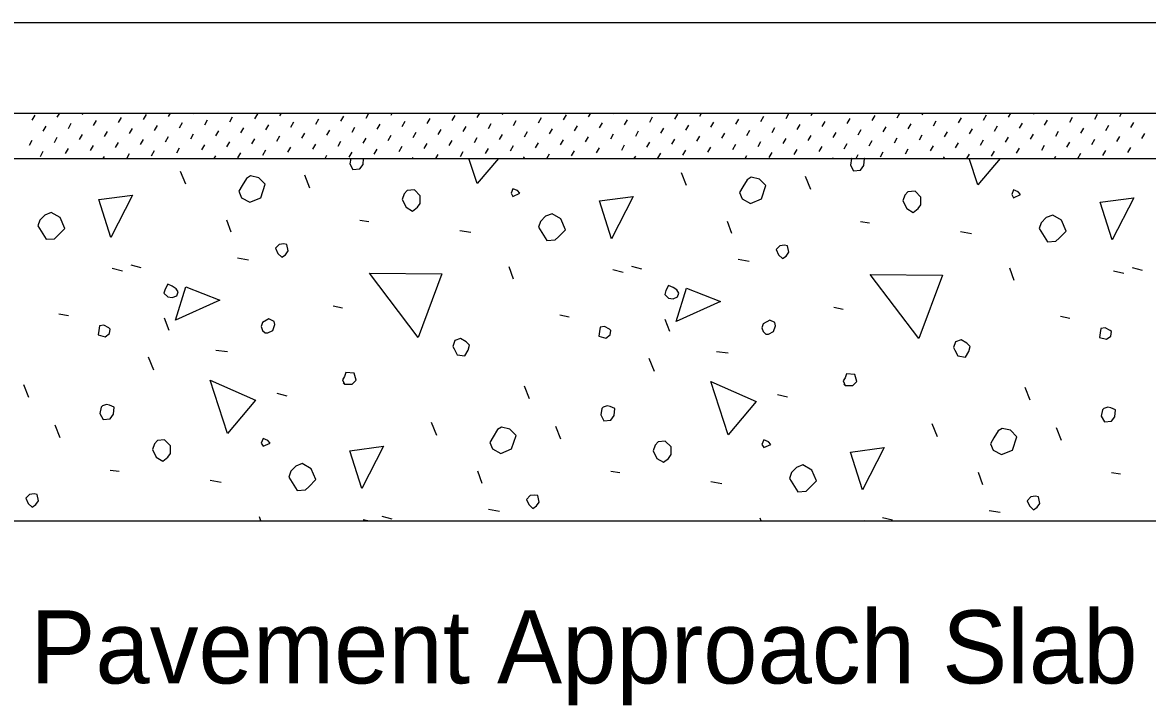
# Model space of a CAD drawing. Extents: x 120631.6 to 120706.2, y 120663.5 to 120716.4.
# Drawn here: x 120657.173 to 120660.279, y 120692.912 to 120694.796 of the extents above; entities that cross this region are included whole.
import ezdxf

# ---------------------------------------------------------------- set-up
doc = ezdxf.new("R2010")
doc.units = 0
for name, color, linetype in [('Dimension', 7, 'Continuous'), ('Miscellaneous', 7, 'Continuous'), ('TrafBarrierConc', 7, 'Continuous')]:
    doc.layers.add(name, color=color, linetype=linetype)

msp = doc.modelspace()

# ---------------------------------------------------------------- linework, layer by layer
at = {"layer": 'Miscellaneous'}
for p, q in [((120657.2001, 120694.5264), (120657.2082, 120694.5404)), ((120657.2693, 120694.5345), (120657.2759, 120694.546)), ((120657.3384, 120694.5426), (120657.3404, 120694.546)), ((120657.5073, 120694.5283), (120657.5154, 120694.5423)), ((120657.5764, 120694.5364), (120657.582, 120694.546)), ((120657.6456, 120694.5445), (120657.6465, 120694.546)), ((120657.8145, 120694.5302), (120657.8226, 120694.5442)), ((120657.8836, 120694.5383), (120657.8881, 120694.546)), ((120658.0525, 120694.524), (120658.0606, 120694.538)), ((120658.1216, 120694.5321), (120658.1297, 120694.546)), ((120658.1908, 120694.5402), (120658.1942, 120694.546)), ((120658.3597, 120694.5258), (120658.3678, 120694.5398)), ((120658.4288, 120694.534), (120658.4358, 120694.546)), ((120658.498, 120694.5421), (120658.5003, 120694.546)), ((120658.6669, 120694.5277), (120658.675, 120694.5417)), ((120658.736, 120694.5358), (120658.7419, 120694.546)), ((120658.8052, 120694.5439), (120658.8064, 120694.546)), ((120658.974, 120694.5296), (120658.9821, 120694.5436)), ((120659.0432, 120694.5377), (120659.048, 120694.546)), ((120659.1124, 120694.5458), (120659.1125, 120694.546)), ((120659.2121, 120694.5234), (120659.2202, 120694.5374)), ((120659.2812, 120694.5315), (120659.2893, 120694.5455)), ((120659.3504, 120694.5396), (120659.3541, 120694.546)), ((120659.5192, 120694.5253), (120659.5274, 120694.5393)), ((120659.5884, 120694.5334), (120659.5957, 120694.546)), ((120659.6576, 120694.5415), (120659.6602, 120694.546)), ((120659.8264, 120694.5271), (120659.8345, 120694.5411)), ((120659.8956, 120694.5352), (120659.9018, 120694.546)), ((120659.9648, 120694.5433), (120659.9663, 120694.546)), ((120660.1336, 120694.529), (120660.1417, 120694.543)), ((120660.2028, 120694.5371), (120660.2079, 120694.546)), ((120660.2719, 120694.5452), (120660.2724, 120694.546)), ((120657.2306, 120694.4959), (120657.2387, 120694.5099)), ((120657.2998, 120694.504), (120657.3079, 120694.518)), ((120657.3689, 120694.5121), (120657.377, 120694.5261)), ((120657.4381, 120694.5202), (120657.4462, 120694.5342)), ((120657.5378, 120694.4978), (120657.5459, 120694.5118)), ((120657.607, 120694.5059), (120657.6151, 120694.5199)), ((120657.6761, 120694.514), (120657.6842, 120694.528)), ((120657.7453, 120694.5221), (120657.7534, 120694.5361)), ((120657.7758, 120694.4916), (120657.7839, 120694.5056)), ((120657.845, 120694.4997), (120657.8531, 120694.5137)), ((120657.9142, 120694.5078), (120657.9223, 120694.5218)), ((120657.9833, 120694.5159), (120657.9914, 120694.5299)), ((120658.083, 120694.4934), (120658.0911, 120694.5074)), ((120658.1522, 120694.5015), (120658.1603, 120694.5155)), ((120658.2213, 120694.5096), (120658.2294, 120694.5236)), ((120658.2905, 120694.5177), (120658.2986, 120694.5317)), ((120658.3902, 120694.4953), (120658.3983, 120694.5093)), ((120658.4594, 120694.5034), (120658.4675, 120694.5174)), ((120658.5285, 120694.5115), (120658.5366, 120694.5255)), ((120658.5977, 120694.5196), (120658.6058, 120694.5336)), ((120658.6974, 120694.4972), (120658.7055, 120694.5112)), ((120658.7665, 120694.5053), (120658.7747, 120694.5193)), ((120658.8357, 120694.5134), (120658.8438, 120694.5274)), ((120658.9049, 120694.5215), (120658.913, 120694.5355)), ((120659.0046, 120694.4991), (120659.0127, 120694.5131)), ((120659.0737, 120694.5072), (120659.0818, 120694.5212)), ((120659.1429, 120694.5153), (120659.151, 120694.5293)), ((120659.2426, 120694.4929), (120659.2507, 120694.5068)), ((120659.3118, 120694.501), (120659.3199, 120694.5149)), ((120659.3809, 120694.5091), (120659.389, 120694.5231)), ((120659.4501, 120694.5172), (120659.4582, 120694.5312)), ((120659.5498, 120694.4947), (120659.5579, 120694.5087)), ((120659.6189, 120694.5028), (120659.627, 120694.5168)), ((120659.6881, 120694.5109), (120659.6962, 120694.5249)), ((120659.7573, 120694.519), (120659.7654, 120694.533)), ((120659.857, 120694.4966), (120659.8651, 120694.5106)), ((120659.9261, 120694.5047), (120659.9342, 120694.5187)), ((120659.9953, 120694.5128), (120660.0034, 120694.5268)), ((120660.0645, 120694.5209), (120660.0726, 120694.5349)), ((120660.1642, 120694.4985), (120660.1723, 120694.5125)), ((120660.2333, 120694.5066), (120660.2414, 120694.5206)), ((120657.2611, 120694.4654), (120657.2693, 120694.4794)), ((120657.3303, 120694.4735), (120657.3384, 120694.4875)), ((120657.3995, 120694.4816), (120657.4076, 120694.4956)), ((120657.4686, 120694.4897), (120657.4767, 120694.5037)), ((120657.5683, 120694.4673), (120657.5764, 120694.4813)), ((120657.6375, 120694.4754), (120657.6456, 120694.4894)), ((120657.7067, 120694.4835), (120657.7148, 120694.4975)), ((120657.8064, 120694.461), (120657.8145, 120694.475)), ((120657.8755, 120694.4691), (120657.8836, 120694.4831)), ((120657.9447, 120694.4772), (120657.9528, 120694.4912)), ((120658.0138, 120694.4853), (120658.022, 120694.4993)), ((120658.1135, 120694.4629), (120658.1216, 120694.4769)), ((120658.1827, 120694.471), (120658.1908, 120694.485)), ((120658.2519, 120694.4791), (120658.26, 120694.4931)), ((120658.321, 120694.4872), (120658.3291, 120694.5012)), ((120658.4207, 120694.4648), (120658.4288, 120694.4788)), ((120658.4899, 120694.4729), (120658.498, 120694.4869)), ((120658.5591, 120694.481), (120658.5672, 120694.495)), ((120658.6282, 120694.4891), (120658.6363, 120694.5031)), ((120658.7279, 120694.4667), (120658.736, 120694.4807)), ((120658.7971, 120694.4748), (120658.8052, 120694.4888)), ((120658.8662, 120694.4829), (120658.8743, 120694.4969)), ((120658.9354, 120694.491), (120658.9435, 120694.505)), ((120658.9659, 120694.4604), (120658.974, 120694.4744)), ((120659.0351, 120694.4685), (120659.0432, 120694.4825)), ((120659.1043, 120694.4766), (120659.1124, 120694.4906)), ((120659.1734, 120694.4847), (120659.1815, 120694.4987)), ((120659.2731, 120694.4623), (120659.2812, 120694.4763)), ((120659.3423, 120694.4704), (120659.3504, 120694.4844)), ((120659.4115, 120694.4785), (120659.4196, 120694.4925)), ((120659.4806, 120694.4866), (120659.4887, 120694.5006)), ((120659.5803, 120694.4642), (120659.5884, 120694.4782)), ((120659.6495, 120694.4723), (120659.6576, 120694.4863)), ((120659.7186, 120694.4804), (120659.7267, 120694.4944)), ((120659.7878, 120694.4885), (120659.7959, 120694.5025)), ((120659.8875, 120694.4661), (120659.8956, 120694.4801)), ((120659.9567, 120694.4742), (120659.9648, 120694.4882)), ((120660.0258, 120694.4823), (120660.0339, 120694.4963)), ((120660.095, 120694.4904), (120660.1031, 120694.5044)), ((120660.1947, 120694.468), (120660.2028, 120694.482)), ((120660.2638, 120694.4761), (120660.2719, 120694.4901)), ((120657.192, 120694.4573), (120657.2001, 120694.4713)), ((120657.2917, 120694.4348), (120657.2998, 120694.4488)), ((120657.3608, 120694.4429), (120657.3689, 120694.4569)), ((120657.43, 120694.4511), (120657.4381, 120694.465)), ((120657.4992, 120694.4592), (120657.5073, 120694.4731)), ((120657.5989, 120694.4367), (120657.607, 120694.4507)), ((120657.668, 120694.4448), (120657.6761, 120694.4588)), ((120657.7372, 120694.4529), (120657.7453, 120694.4669)), ((120657.8369, 120694.4305), (120657.845, 120694.4445)), ((120657.9061, 120694.4386), (120657.9142, 120694.4526)), ((120657.9752, 120694.4467), (120657.9833, 120694.4607)), ((120658.0444, 120694.4548), (120658.0525, 120694.4688)), ((120658.1441, 120694.4324), (120658.1522, 120694.4464)), ((120658.2132, 120694.4405), (120658.2213, 120694.4545)), ((120658.2824, 120694.4486), (120658.2905, 120694.4626)), ((120658.3516, 120694.4567), (120658.3597, 120694.4707)), ((120658.4513, 120694.4343), (120658.4594, 120694.4483)), ((120658.5204, 120694.4424), (120658.5285, 120694.4564)), ((120658.5896, 120694.4505), (120658.5977, 120694.4645)), ((120658.6588, 120694.4586), (120658.6669, 120694.4726)), ((120658.7584, 120694.4361), (120658.7665, 120694.4501)), ((120658.8276, 120694.4442), (120658.8357, 120694.4582)), ((120658.8968, 120694.4523), (120658.9049, 120694.4663)), ((120658.9965, 120694.4299), (120659.0046, 120694.4439)), ((120659.0656, 120694.438), (120659.0737, 120694.452)), ((120659.1348, 120694.4461), (120659.1429, 120694.4601)), ((120659.204, 120694.4542), (120659.2121, 120694.4682)), ((120659.3037, 120694.4318), (120659.3118, 120694.4458)), ((120659.3728, 120694.4399), (120659.3809, 120694.4539)), ((120659.442, 120694.448), (120659.4501, 120694.462)), ((120659.5111, 120694.4561), (120659.5192, 120694.4701)), ((120659.6108, 120694.4337), (120659.6189, 120694.4477)), ((120659.68, 120694.4418), (120659.6881, 120694.4558)), ((120659.7492, 120694.4499), (120659.7573, 120694.4639)), ((120659.8183, 120694.458), (120659.8264, 120694.472)), ((120659.918, 120694.4355), (120659.9261, 120694.4495)), ((120659.9872, 120694.4436), (120659.9953, 120694.4576)), ((120660.0564, 120694.4518), (120660.0645, 120694.4657)), ((120660.1255, 120694.4599), (120660.1336, 120694.4738)), ((120660.1561, 120694.4293), (120660.1642, 120694.4433)), ((120660.2252, 120694.4374), (120660.2333, 120694.4514)), ((120657.2225, 120694.4267), (120657.2306, 120694.4407)), ((120657.3963, 120694.421), (120657.3995, 120694.4264)), ((120657.4608, 120694.421), (120657.4686, 120694.4345)), ((120657.5297, 120694.4286), (120657.5378, 120694.4426)), ((120657.7024, 120694.421), (120657.7067, 120694.4283)), ((120657.7677, 120694.4224), (120657.7758, 120694.4364)), ((120657.9441, 120694.421), (120657.9447, 120694.4221)), ((120658.0085, 120694.421), (120658.0138, 120694.4302)), ((120658.0749, 120694.4243), (120658.083, 120694.4383)), ((120658.2502, 120694.421), (120658.2519, 120694.4239)), ((120658.3146, 120694.421), (120658.321, 120694.432)), ((120658.3821, 120694.4262), (120658.3902, 120694.4401)), ((120658.5563, 120694.421), (120658.5591, 120694.4258)), ((120658.6207, 120694.421), (120658.6282, 120694.4339)), ((120658.6893, 120694.428), (120658.6974, 120694.442)), ((120658.8624, 120694.421), (120658.8662, 120694.4277)), ((120658.9273, 120694.4218), (120658.9354, 120694.4358)), ((120659.104, 120694.421), (120659.1043, 120694.4215)), ((120659.1685, 120694.421), (120659.1734, 120694.4296)), ((120659.2345, 120694.4237), (120659.2426, 120694.4377)), ((120659.4101, 120694.421), (120659.4115, 120694.4234)), ((120659.4746, 120694.421), (120659.4806, 120694.4315)), ((120659.5417, 120694.4256), (120659.5498, 120694.4396)), ((120659.7162, 120694.421), (120659.7186, 120694.4252)), ((120659.7807, 120694.421), (120659.7878, 120694.4333)), ((120659.8489, 120694.4274), (120659.857, 120694.4414)), ((120660.0223, 120694.421), (120660.0258, 120694.4271)), ((120660.0869, 120694.4212), (120660.095, 120694.4352)), ((120657.6239, 120694.3499), (120657.6098, 120694.3852)), ((120659.0063, 120694.3464), (120658.9922, 120694.3817)), ((120657.9669, 120694.3393), (120657.9527, 120694.3746)), ((120659.3493, 120694.3358), (120659.3351, 120694.3711)), ((120657.7495, 120694.2173), (120657.7371, 120694.2509)), ((120658.1048, 120694.2509), (120658.1295, 120694.2474)), ((120659.1318, 120694.2138), (120659.1195, 120694.2474)), ((120659.4872, 120694.2474), (120659.5119, 120694.2438)), ((120658.3805, 120694.2226), (120658.4106, 120694.2173)), ((120659.7629, 120694.2191), (120659.793, 120694.2138)), ((120657.7671, 120694.1466), (120657.7972, 120694.1413)), ((120659.1495, 120694.1431), (120659.1796, 120694.1378)), ((120657.4206, 120694.1183), (120657.4489, 120694.1112)), ((120657.4719, 120694.1272), (120657.5002, 120694.1201)), ((120658.529, 120694.0883), (120658.5167, 120694.1219)), ((120658.803, 120694.1148), (120658.8313, 120694.1077)), ((120658.8543, 120694.1236), (120658.8826, 120694.1165)), ((120659.9114, 120694.0847), (120659.8991, 120694.1183)), ((120660.1854, 120694.1112), (120660.2137, 120694.1042)), ((120660.2367, 120694.1201), (120660.265, 120694.113)), ((120658.0305, 120694.014), (120658.057, 120694.0087)), ((120659.4129, 120694.0105), (120659.4394, 120694.0052)), ((120657.2739, 120693.9928), (120657.3004, 120693.9875)), ((120657.578, 120693.9468), (120657.5656, 120693.9804)), ((120658.6563, 120693.9893), (120658.6828, 120693.984)), ((120660.0387, 120693.9857), (120660.0652, 120693.9804)), ((120658.9604, 120693.9433), (120658.948, 120693.9769)), ((120657.707, 120693.892), (120657.7388, 120693.8885)), ((120659.0894, 120693.8885), (120659.1212, 120693.885)), ((120657.5356, 120693.8372), (120657.5214, 120693.8726)), ((120658.9179, 120693.8337), (120658.9038, 120693.8691)), ((120657.1908, 120693.7612), (120657.1767, 120693.7966)), ((120658.5732, 120693.7577), (120658.5591, 120693.793)), ((120657.875, 120693.7736), (120657.9032, 120693.7665)), ((120659.2574, 120693.7701), (120659.2856, 120693.763)), ((120659.9556, 120693.7542), (120659.9415, 120693.7895)), ((120657.2775, 120693.6499), (120657.2633, 120693.6852)), ((120658.3169, 120693.6569), (120658.3028, 120693.6923)), ((120658.6599, 120693.6463), (120658.6457, 120693.6817)), ((120659.6993, 120693.6534), (120659.6852, 120693.6887)), ((120660.0422, 120693.6428), (120660.0281, 120693.6781)), ((120657.4153, 120693.5615), (120657.4401, 120693.5579)), ((120658.4424, 120693.5243), (120658.43, 120693.5579)), ((120658.7977, 120693.5579), (120658.8225, 120693.5544)), ((120659.8248, 120693.5208), (120659.8124, 120693.5544)), ((120660.1801, 120693.5544), (120660.2049, 120693.5509)), ((120657.6911, 120693.5332), (120657.7212, 120693.5279)), ((120659.0735, 120693.5296), (120659.1036, 120693.5243)), ((120658.4601, 120693.4536), (120658.4901, 120693.4483)), ((120659.8425, 120693.4501), (120659.8725, 120693.4448)), ((120657.8314, 120693.421), (120657.8272, 120693.4324)), ((120658.1136, 120693.4254), (120658.131, 120693.421)), ((120658.1649, 120693.4342), (120658.1932, 120693.4271)), ((120659.2125, 120693.421), (120659.2096, 120693.4289)), ((120659.496, 120693.4218), (120659.4992, 120693.421)), ((120659.5473, 120693.4307), (120659.5756, 120693.4236))]:
    msp.add_line(p, q, dxfattribs=at)
for points in [[(120658.0765, 120694.4065), (120658.0853, 120694.3906), (120658.1048, 120694.3923), (120658.1136, 120694.4047), (120658.1151, 120694.421)], [(120658.0794, 120694.421), (120658.0765, 120694.4065)], [(120658.4283, 120694.3517), (120658.4057, 120694.421)], [(120658.487, 120694.421), (120658.4283, 120694.3517)], [(120659.4589, 120694.4029), (120659.4677, 120694.387), (120659.4872, 120694.3888), (120659.496, 120694.4012), (120659.4978, 120694.4206), (120659.4968, 120694.421)], [(120659.4628, 120694.421), (120659.4624, 120694.4206), (120659.4589, 120694.4029)], [(120659.8107, 120694.3481), (120659.787, 120694.421)], [(120659.8723, 120694.421), (120659.8107, 120694.3481)], [(120657.7777, 120694.3128), (120657.8007, 120694.3004), (120657.8308, 120694.3128), (120657.8431, 120694.3499), (120657.8255, 120694.3676), (120657.8025, 120694.3729), (120657.7919, 120694.3658), (120657.7795, 120694.3464), (120657.7707, 120694.3304), (120657.7777, 120694.3128)], [(120659.1601, 120694.3092), (120659.1831, 120694.2969), (120659.2132, 120694.3092), (120659.2255, 120694.3464), (120659.2079, 120694.364), (120659.1849, 120694.3693), (120659.1743, 120694.3623), (120659.1619, 120694.3428), (120659.1531, 120694.3269), (120659.1601, 120694.3092)], [(120657.4171, 120694.2032), (120657.3835, 120694.3075), (120657.4772, 120694.3198), (120657.4171, 120694.2032)], [(120658.2214, 120694.3075), (120658.2321, 120694.2863), (120658.2497, 120694.2756), (120658.2639, 120694.2863), (120658.2709, 120694.2969), (120658.2709, 120694.3181), (120658.255, 120694.334), (120658.2356, 120694.3322), (120658.2267, 120694.3234), (120658.2214, 120694.3075)], [(120658.5273, 120694.3163), (120658.5467, 120694.3251), (120658.5396, 120694.3322), (120658.5273, 120694.3375), (120658.522, 120694.3251), (120658.5273, 120694.3163)], [(120659.6038, 120694.3039), (120659.6144, 120694.2827), (120659.6321, 120694.2721), (120659.6463, 120694.2827), (120659.6533, 120694.2933), (120659.6533, 120694.3145), (120659.6374, 120694.3304), (120659.618, 120694.3287), (120659.6091, 120694.3198), (120659.6038, 120694.3039)], [(120659.9097, 120694.3128), (120659.9291, 120694.3216), (120659.922, 120694.3287), (120659.9097, 120694.334), (120659.9044, 120694.3216), (120659.9097, 120694.3128)], [(120658.7995, 120694.1996), (120658.7659, 120694.3039), (120658.8596, 120694.3163), (120658.7995, 120694.1996)], [(120660.1819, 120694.1961), (120660.1483, 120694.3004), (120660.242, 120694.3128), (120660.1819, 120694.1961)], [(120657.2156, 120694.235), (120657.2386, 120694.1979), (120657.2615, 120694.1996), (120657.2704, 120694.2085), (120657.2898, 120694.2279), (120657.2775, 120694.258), (120657.2527, 120694.2721), (120657.235, 120694.265), (120657.2209, 120694.2509), (120657.2156, 120694.235)], [(120658.598, 120694.2315), (120658.621, 120694.1943), (120658.6439, 120694.1961), (120658.6528, 120694.2049), (120658.6722, 120694.2244), (120658.6599, 120694.2544), (120658.6351, 120694.2686), (120658.6174, 120694.2615), (120658.6033, 120694.2474), (120658.598, 120694.2315)], [(120659.9804, 120694.2279), (120660.0034, 120694.1908), (120660.0263, 120694.1926), (120660.0352, 120694.2014), (120660.0546, 120694.2208), (120660.0422, 120694.2509), (120660.0175, 120694.265), (120659.9998, 120694.258), (120659.9857, 120694.2438), (120659.9804, 120694.2279)], [(120657.8785, 120694.159), (120657.8891, 120694.1484), (120657.8997, 120694.1554), (120657.9068, 120694.166), (120657.9032, 120694.1837), (120657.8944, 120694.1855), (120657.882, 120694.1837), (120657.8714, 120694.1731), (120657.8785, 120694.159)], [(120659.2609, 120694.1554), (120659.2715, 120694.1448), (120659.2821, 120694.1519), (120659.2892, 120694.1625), (120659.2856, 120694.1802), (120659.2768, 120694.182), (120659.2644, 120694.1802), (120659.2538, 120694.1696), (120659.2609, 120694.1554)], [(120658.2656, 120693.9274), (120658.1313, 120694.1042), (120658.331, 120694.1024), (120658.2656, 120693.9274)], [(120657.5744, 120694.0388), (120657.5868, 120694.037), (120657.5992, 120694.0423), (120657.6027, 120694.0529), (120657.5974, 120694.0617), (120657.5868, 120694.0688), (120657.5744, 120694.0741), (120657.5674, 120694.06), (120657.5638, 120694.0494), (120657.5744, 120694.0388)], [(120658.9568, 120694.0352), (120658.9692, 120694.0335), (120658.9816, 120694.0388), (120658.9851, 120694.0494), (120658.9798, 120694.0582), (120658.9692, 120694.0653), (120658.9568, 120694.0706), (120658.9498, 120694.0564), (120658.9462, 120694.0458), (120658.9568, 120694.0352)], [(120659.648, 120693.9239), (120659.5137, 120694.1006), (120659.7134, 120694.0989), (120659.648, 120693.9239)], [(120657.5957, 120693.9751), (120657.6239, 120694.067), (120657.7176, 120694.0299), (120657.5957, 120693.9751)], [(120658.978, 120693.9716), (120659.0063, 120694.0635), (120659.1, 120694.0264), (120658.978, 120693.9716)], [(120657.8431, 120693.9398), (120657.8502, 120693.9398), (120657.8644, 120693.9468), (120657.8697, 120693.9628), (120657.8679, 120693.9716), (120657.8537, 120693.9787), (120657.8361, 120693.9681), (120657.8325, 120693.9574), (120657.8361, 120693.9468), (120657.8431, 120693.9398)], [(120657.3818, 120693.9345), (120657.4012, 120693.9292), (120657.4136, 120693.938), (120657.4153, 120693.9504), (120657.4118, 120693.9539), (120657.3977, 120693.961), (120657.3853, 120693.9592), (120657.3835, 120693.9468), (120657.3818, 120693.9345)], [(120658.7641, 120693.9309), (120658.7836, 120693.9256), (120658.796, 120693.9345), (120658.7977, 120693.9468), (120658.7942, 120693.9504), (120658.7801, 120693.9574), (120658.7677, 120693.9557), (120658.7659, 120693.9433), (120658.7641, 120693.9309)], [(120659.2255, 120693.9362), (120659.2326, 120693.9362), (120659.2467, 120693.9433), (120659.2521, 120693.9592), (120659.2503, 120693.9681), (120659.2361, 120693.9751), (120659.2185, 120693.9645), (120659.2149, 120693.9539), (120659.2185, 120693.9433), (120659.2255, 120693.9362)], [(120660.1465, 120693.9274), (120660.166, 120693.9221), (120660.1784, 120693.9309), (120660.1801, 120693.9433), (120660.1766, 120693.9468), (120660.1625, 120693.9539), (120660.1501, 120693.9521), (120660.1483, 120693.9398), (120660.1465, 120693.9274)], [(120658.3646, 120693.8956), (120658.3735, 120693.8797), (120658.3947, 120693.8761), (120658.4035, 120693.892), (120658.4071, 120693.9062), (120658.3982, 120693.915), (120658.3823, 120693.9239), (120658.3664, 120693.9186), (120658.3611, 120693.9026), (120658.3646, 120693.8956)], [(120659.747, 120693.892), (120659.7559, 120693.8761), (120659.7771, 120693.8726), (120659.7859, 120693.8885), (120659.7895, 120693.9026), (120659.7806, 120693.9115), (120659.7647, 120693.9203), (120659.7488, 120693.915), (120659.7435, 120693.8991), (120659.747, 120693.892)], [(120658.0623, 120693.7983), (120658.0836, 120693.7983), (120658.0942, 120693.809), (120658.0889, 120693.8284), (120658.0659, 120693.8302), (120658.0623, 120693.8196), (120658.057, 120693.8107), (120658.0623, 120693.7983), (120658.0588, 120693.8019)], [(120659.4447, 120693.7948), (120659.466, 120693.7948), (120659.4766, 120693.8054), (120659.4713, 120693.8249), (120659.4483, 120693.8266), (120659.4447, 120693.816), (120659.4394, 120693.8072), (120659.4447, 120693.7948), (120659.4412, 120693.7983)], [(120657.7388, 120693.6622), (120657.6911, 120693.809), (120657.8166, 120693.7542), (120657.7388, 120693.6622)], [(120659.1212, 120693.6587), (120659.0735, 120693.8054), (120659.199, 120693.7506), (120659.1212, 120693.6587)], [(120657.3871, 120693.717), (120657.3959, 120693.7011), (120657.4153, 120693.7029), (120657.4242, 120693.7153), (120657.426, 120693.7347), (120657.4136, 120693.74), (120657.4047, 120693.7418), (120657.3941, 120693.7382), (120657.3906, 120693.7347), (120657.3871, 120693.717)], [(120658.7695, 120693.7135), (120658.7783, 120693.6976), (120658.7977, 120693.6994), (120658.8066, 120693.7117), (120658.8083, 120693.7312), (120658.796, 120693.7365), (120658.7871, 120693.7382), (120658.7765, 120693.7347), (120658.773, 120693.7312), (120658.7695, 120693.7135)], [(120660.1518, 120693.71), (120660.1607, 120693.6941), (120660.1801, 120693.6958), (120660.189, 120693.7082), (120660.1907, 120693.7276), (120660.1784, 120693.7329), (120660.1695, 120693.7347), (120660.1589, 120693.7312), (120660.1554, 120693.7276), (120660.1518, 120693.71)], [(120658.4707, 120693.6198), (120658.4937, 120693.6074), (120658.5237, 120693.6198), (120658.5361, 120693.6569), (120658.5184, 120693.6746), (120658.4954, 120693.6799), (120658.4848, 120693.6728), (120658.4725, 120693.6534), (120658.4636, 120693.6375), (120658.4707, 120693.6198)], [(120659.8531, 120693.6163), (120659.8761, 120693.6039), (120659.9061, 120693.6163), (120659.9185, 120693.6534), (120659.9008, 120693.6711), (120659.8778, 120693.6764), (120659.8672, 120693.6693), (120659.8549, 120693.6499), (120659.846, 120693.6339), (120659.8531, 120693.6163)], [(120657.532, 120693.618), (120657.5426, 120693.5968), (120657.5603, 120693.5862), (120657.5744, 120693.5968), (120657.5815, 120693.6074), (120657.5815, 120693.6286), (120657.5656, 120693.6446), (120657.5462, 120693.6428), (120657.5373, 120693.6339), (120657.532, 120693.618)], [(120657.8378, 120693.6269), (120657.8573, 120693.6357), (120657.8502, 120693.6428), (120657.8378, 120693.6481), (120657.8325, 120693.6357), (120657.8378, 120693.6269)], [(120658.9144, 120693.6145), (120658.925, 120693.5933), (120658.9427, 120693.5827), (120658.9568, 120693.5933), (120658.9639, 120693.6039), (120658.9639, 120693.6251), (120658.948, 120693.641), (120658.9286, 120693.6392), (120658.9197, 120693.6304), (120658.9144, 120693.6145)], [(120659.2202, 120693.6233), (120659.2397, 120693.6322), (120659.2326, 120693.6392), (120659.2202, 120693.6446), (120659.2149, 120693.6322), (120659.2202, 120693.6233)], [(120658.1101, 120693.5102), (120658.0765, 120693.6145), (120658.1702, 120693.6269), (120658.1101, 120693.5102)], [(120659.4925, 120693.5067), (120659.4589, 120693.611), (120659.5526, 120693.6233), (120659.4925, 120693.5067)], [(120657.9086, 120693.542), (120657.9315, 120693.5049), (120657.9545, 120693.5067), (120657.9634, 120693.5155), (120657.9828, 120693.535), (120657.9704, 120693.565), (120657.9457, 120693.5791), (120657.928, 120693.5721), (120657.9139, 120693.5579), (120657.9086, 120693.542)], [(120659.2909, 120693.5385), (120659.3139, 120693.5014), (120659.3369, 120693.5031), (120659.3457, 120693.512), (120659.3652, 120693.5314), (120659.3528, 120693.5615), (120659.3281, 120693.5756), (120659.3104, 120693.5685), (120659.2962, 120693.5544), (120659.2909, 120693.5385)], [(120657.1891, 120693.4695), (120657.1997, 120693.4589), (120657.2103, 120693.466), (120657.2174, 120693.4766), (120657.2138, 120693.4943), (120657.205, 120693.4961), (120657.1926, 120693.4943), (120657.182, 120693.4837), (120657.1891, 120693.4695)], [(120658.5715, 120693.466), (120658.5821, 120693.4554), (120658.5927, 120693.4625), (120658.5997, 120693.4731), (120658.5962, 120693.4908), (120658.5874, 120693.4925), (120658.575, 120693.4908), (120658.5644, 120693.4802), (120658.5715, 120693.466)], [(120659.9539, 120693.4625), (120659.9645, 120693.4519), (120659.9751, 120693.4589), (120659.9821, 120693.4695), (120659.9786, 120693.4872), (120659.9698, 120693.489), (120659.9574, 120693.4872), (120659.9468, 120693.4766), (120659.9539, 120693.4625)]]:
    msp.add_lwpolyline(points, dxfattribs=at)
at = {"layer": 'TrafBarrierConc'}
for p, q in [((120654.2962, 120694.7961), (120670.1273, 120694.7961)), ((120654.2962, 120694.5461), (120670.1273, 120694.5461)), ((120654.2962, 120694.421), (120670.1273, 120694.421)), ((120654.2962, 120693.4211), (120670.1273, 120693.4211))]:
    msp.add_line(p, q, dxfattribs=at)

# ---------------------------------------------------------------- texts
at = {"layer": 'Dimension'}
msp.add_text('Approach Slab (Flexible Pavement Approach Slab ', height=0.2016, dxfattribs=at).set_placement((120654.2576, 120692.9727))

doc.saveas('drawing.dxf')
